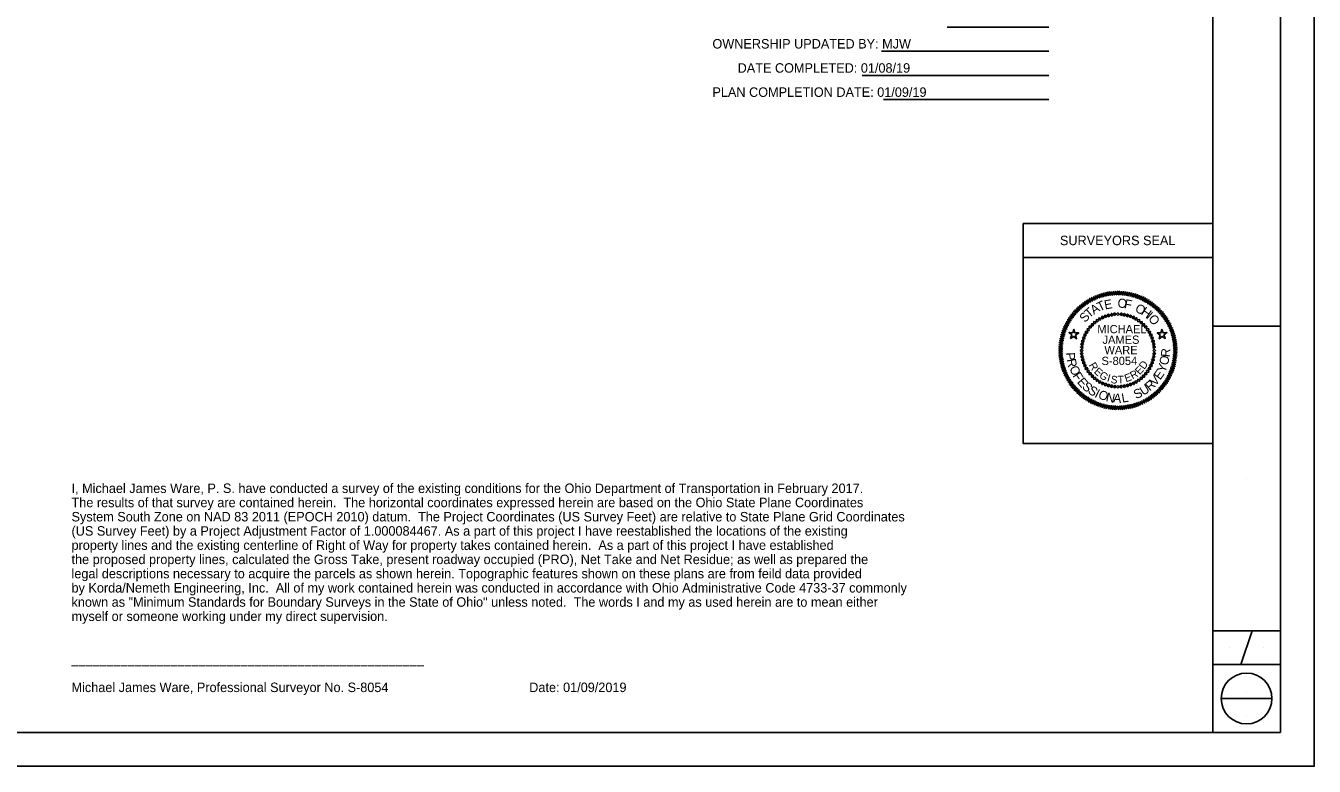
# Model space of a CAD drawing. Extents: x -0.4 to 33.6, y -0.9 to 21.1.
# Drawn here: x 14.55 to 33.59, y -0.92 to 10.01 of the extents above; entities that cross this region are included whole.
import ezdxf

# ---------------------------------------------------------------- set-up
doc = ezdxf.new("R2010")
doc.units = 0
for name, color, linetype in [('SH_Border', 7, 'Continuous'), ('SH_Cut_Line', 7, 'Continuous'), ('SH_Data', 7, 'Continuous'), ('SH_Text', 7, 'Continuous')]:
    doc.layers.add(name, color=color, linetype=linetype)

msp = doc.modelspace()

# ---------------------------------------------------------------- linework, layer by layer
at = {"layer": 'SH_Border'}
for p, q in [((32.087, -0.423), (32.087, 20.577)), ((32.087, 5.577), (33.087, 5.577)), ((32.087, 1.077), (33.087, 1.077)), ((32.504, 0.577), (32.67, 1.077)), ((32.087, 0.577), (33.087, 0.577))]:
    msp.add_line(p, q, dxfattribs=at)
msp.add_lwpolyline([(1.587, 20.577), (33.087, 20.577), (33.087, -0.423), (1.587, -0.423)], close=True, dxfattribs=at)
at = {"layer": 'SH_Cut_Line'}
msp.add_lwpolyline([(-0.413, -0.923), (33.587, -0.923), (33.587, 21.077), (-0.413, 21.077)], close=True, dxfattribs=at)
at = {"layer": 'SH_Data'}
for p, q in [((29.287, 6.592), (32.087, 6.592)), ((32.587, 3.327), (32.587, 3.327)), ((32.336, 0.827), (32.336, 0.827)), ((32.836, 0.827), (32.836, 0.827)), ((32.212, 0.077), (32.962, 0.077)), ((32.587, 0.162), (32.587, 0.162)), ((32.587, -0.178), (32.587, -0.178))]:
    msp.add_line(p, q, dxfattribs=at)
msp.add_lwpolyline([(29.287, 7.092), (32.087, 7.092), (32.087, 3.842), (29.287, 3.842)], close=True, dxfattribs=at)
msp.add_circle((32.587, 0.077), 0.375, dxfattribs=at)
at = {"layer": 'SH_Text'}
for p, q in [((28.162, 9.993), (29.665, 9.993)), ((27.192, 9.636), (29.665, 9.636)), ((26.906, 9.279), (29.665, 9.279)), ((27.221, 8.922), (29.665, 8.922)), ((30.641, 6.032), (30.614, 6.093)), ((30.67, 6.033), (30.645, 6.095)), ((30.698, 6.033), (30.675, 6.096)), ((30.727, 6.032), (30.706, 6.096)), ((30.755, 6.03), (30.737, 6.095)), ((30.784, 6.027), (30.767, 6.092)), ((30.194, 5.867), (30.137, 5.903)), ((30.217, 5.884), (30.161, 5.921)), ((30.24, 5.9), (30.186, 5.939)), ((30.264, 5.915), (30.211, 5.956)), ((30.289, 5.93), (30.238, 5.972)), ((30.314, 5.943), (30.264, 5.988)), ((30.339, 5.956), (30.291, 6.002)), ((30.365, 5.967), (30.319, 6.015)), ((30.392, 5.978), (30.347, 6.028)), ((30.419, 5.988), (30.376, 6.039)), ((30.446, 5.997), (30.404, 6.049)), ((30.473, 6.005), (30.434, 6.059)), ((30.501, 6.012), (30.463, 6.067)), ((30.528, 6.018), (30.493, 6.074)), ((30.556, 6.023), (30.523, 6.081)), ((30.585, 6.027), (30.553, 6.086)), ((30.613, 6.03), (30.584, 6.09)), ((30.812, 6.024), (30.798, 6.089)), ((30.84, 6.019), (30.828, 6.085)), ((30.868, 6.013), (30.858, 6.079)), ((30.895, 6.006), (30.888, 6.073)), ((30.923, 5.998), (30.918, 6.065)), ((30.95, 5.99), (30.948, 6.056)), ((30.977, 5.98), (30.977, 6.047)), ((31.003, 5.969), (31.005, 6.036)), ((31.029, 5.958), (31.034, 6.025)), ((31.055, 5.946), (31.062, 6.012)), ((31.08, 5.932), (31.089, 5.998)), ((31.105, 5.918), (31.116, 5.984)), ((31.129, 5.903), (31.143, 5.968)), ((31.153, 5.887), (31.169, 5.952)), ((31.176, 5.871), (31.194, 5.935)), ((31.198, 5.853), (31.219, 5.917)), ((30.033, 5.706), (29.969, 5.724)), ((30.051, 5.729), (29.987, 5.749)), ((30.069, 5.75), (30.006, 5.773)), ((30.088, 5.772), (30.026, 5.797)), ((30.108, 5.792), (30.047, 5.819)), ((30.128, 5.812), (30.068, 5.841)), ((30.149, 5.831), (30.09, 5.863)), ((30.171, 5.85), (30.113, 5.883)), ((31.22, 5.835), (31.243, 5.898)), ((31.241, 5.816), (31.266, 5.878)), ((31.262, 5.796), (31.289, 5.857)), ((31.282, 5.776), (31.311, 5.836)), ((31.301, 5.755), (31.332, 5.814)), ((31.319, 5.733), (31.353, 5.791)), ((31.337, 5.711), (31.372, 5.767)), ((31.354, 5.688), (31.391, 5.743)), ((31.37, 5.664), (31.409, 5.718)), ((29.935, 5.533), (29.868, 5.536)), ((29.946, 5.56), (29.879, 5.564)), ((29.959, 5.585), (29.892, 5.592)), ((29.972, 5.61), (29.906, 5.62)), ((29.986, 5.635), (29.92, 5.647)), ((30.001, 5.659), (29.936, 5.673)), ((30.017, 5.683), (29.952, 5.699)), ((31.385, 5.64), (31.426, 5.693)), ((31.399, 5.615), (31.442, 5.666)), ((31.413, 5.59), (31.457, 5.64)), ((31.425, 5.565), (31.472, 5.613)), ((31.437, 5.539), (31.485, 5.585)), ((31.448, 5.512), (31.497, 5.557)), ((31.457, 5.486), (31.509, 5.528)), ((29.88, 5.342), (29.815, 5.328)), ((29.885, 5.37), (29.819, 5.359)), ((29.891, 5.398), (29.825, 5.389)), ((29.898, 5.426), (29.831, 5.419)), ((29.906, 5.453), (29.839, 5.448)), ((29.914, 5.48), (29.848, 5.478)), ((29.924, 5.507), (29.857, 5.507)), ((31.466, 5.458), (31.519, 5.5)), ((31.474, 5.431), (31.528, 5.47)), ((31.481, 5.403), (31.537, 5.441)), ((31.487, 5.376), (31.544, 5.411)), ((31.492, 5.348), (31.55, 5.381)), ((31.496, 5.319), (31.555, 5.351)), ((29.872, 5.257), (29.808, 5.236)), ((29.871, 5.229), (29.808, 5.206)), ((29.874, 5.286), (29.809, 5.267)), ((29.871, 5.2), (29.809, 5.175)), ((29.872, 5.172), (29.811, 5.144)), ((29.877, 5.314), (29.812, 5.298)), ((29.874, 5.143), (29.814, 5.114)), ((31.499, 5.291), (31.56, 5.32)), ((31.5, 5.149), (31.564, 5.167)), ((31.502, 5.263), (31.563, 5.29)), ((31.502, 5.177), (31.565, 5.198)), ((31.503, 5.234), (31.565, 5.259)), ((31.503, 5.206), (31.566, 5.229)), ((29.877, 5.115), (29.818, 5.084)), ((29.881, 5.087), (29.823, 5.053)), ((29.886, 5.059), (29.83, 5.023)), ((29.892, 5.031), (29.837, 4.994)), ((29.899, 5.003), (29.845, 4.964)), ((29.907, 4.976), (29.855, 4.935)), ((31.459, 4.954), (31.526, 4.957)), ((31.468, 4.981), (31.535, 4.986)), ((31.476, 5.009), (31.542, 5.016)), ((31.483, 5.036), (31.549, 5.046)), ((31.488, 5.064), (31.554, 5.076)), ((31.493, 5.092), (31.559, 5.106)), ((31.497, 5.121), (31.562, 5.137)), ((29.916, 4.949), (29.865, 4.906)), ((29.926, 4.922), (29.876, 4.877)), ((29.937, 4.896), (29.889, 4.849)), ((29.948, 4.87), (29.902, 4.822)), ((29.961, 4.844), (29.916, 4.795)), ((29.975, 4.819), (29.932, 4.768)), ((29.989, 4.795), (29.948, 4.742)), ((30.004, 4.77), (29.965, 4.716)), ((31.373, 4.775), (31.438, 4.761)), ((31.388, 4.799), (31.454, 4.788)), ((31.402, 4.824), (31.468, 4.815)), ((31.415, 4.849), (31.482, 4.842)), ((31.428, 4.875), (31.494, 4.87)), ((31.439, 4.901), (31.506, 4.899)), ((31.45, 4.927), (31.517, 4.927)), ((30.02, 4.747), (29.983, 4.691)), ((30.037, 4.724), (30.001, 4.667)), ((30.054, 4.701), (30.021, 4.644)), ((30.073, 4.68), (30.041, 4.621)), ((30.092, 4.659), (30.063, 4.599)), ((30.112, 4.638), (30.085, 4.577)), ((30.132, 4.618), (30.107, 4.556)), ((30.154, 4.6), (30.131, 4.537)), ((30.176, 4.581), (30.155, 4.518)), ((31.203, 4.585), (31.26, 4.551)), ((31.224, 4.603), (31.283, 4.572)), ((31.245, 4.622), (31.306, 4.593)), ((31.266, 4.642), (31.327, 4.615)), ((31.286, 4.663), (31.348, 4.638)), ((31.305, 4.684), (31.367, 4.661)), ((31.323, 4.706), (31.386, 4.685)), ((31.34, 4.728), (31.404, 4.71)), ((31.357, 4.751), (31.422, 4.735)), ((30.198, 4.564), (30.18, 4.5)), ((30.221, 4.547), (30.205, 4.482)), ((30.245, 4.531), (30.231, 4.466)), ((30.269, 4.516), (30.257, 4.45)), ((30.294, 4.502), (30.284, 4.436)), ((30.319, 4.489), (30.312, 4.422)), ((30.345, 4.476), (30.34, 4.41)), ((30.371, 4.465), (30.368, 4.398)), ((30.397, 4.454), (30.397, 4.388)), ((30.424, 4.445), (30.426, 4.378)), ((30.451, 4.436), (30.456, 4.369)), ((30.478, 4.428), (30.485, 4.362)), ((30.506, 4.421), (30.515, 4.355)), ((30.534, 4.416), (30.546, 4.35)), ((30.562, 4.411), (30.576, 4.345)), ((30.59, 4.407), (30.606, 4.342)), ((30.619, 4.404), (30.637, 4.34)), ((30.647, 4.402), (30.668, 4.339)), ((30.675, 4.401), (30.698, 4.338)), ((30.704, 4.401), (30.729, 4.339)), ((30.732, 4.402), (30.76, 4.341)), ((30.761, 4.405), (30.79, 4.344)), ((30.789, 4.408), (30.82, 4.349)), ((30.817, 4.412), (30.851, 4.354)), ((30.845, 4.417), (30.881, 4.36)), ((30.873, 4.423), (30.911, 4.367)), ((30.901, 4.43), (30.94, 4.376)), ((30.928, 4.438), (30.969, 4.385)), ((30.955, 4.447), (30.998, 4.395)), ((30.982, 4.456), (31.027, 4.407)), ((31.008, 4.467), (31.055, 4.419)), ((31.034, 4.479), (31.082, 4.432)), ((31.06, 4.491), (31.109, 4.447)), ((31.085, 4.505), (31.136, 4.462)), ((31.11, 4.519), (31.162, 4.478)), ((31.134, 4.534), (31.188, 4.495)), ((31.157, 4.55), (31.213, 4.513)), ((31.18, 4.567), (31.237, 4.532))]:
    msp.add_line(p, q, dxfattribs=at)
for points in [[(30.469, 5.685), (30.478, 5.712), (30.452, 5.721), (30.442, 5.695)], [(30.51, 5.702), (30.522, 5.728), (30.497, 5.74), (30.485, 5.714)], [(30.553, 5.716), (30.567, 5.74), (30.543, 5.754), (30.529, 5.73)], [(30.597, 5.725), (30.613, 5.749), (30.59, 5.765), (30.574, 5.742)], [(30.642, 5.731), (30.66, 5.753), (30.638, 5.771), (30.62, 5.75)], [(30.687, 5.733), (30.707, 5.753), (30.687, 5.773), (30.667, 5.753)], [(30.732, 5.731), (30.753, 5.75), (30.735, 5.771), (30.714, 5.753)], [(30.776, 5.725), (30.8, 5.742), (30.783, 5.765), (30.76, 5.749)], [(30.82, 5.716), (30.845, 5.73), (30.831, 5.754), (30.806, 5.74)], [(30.863, 5.702), (30.889, 5.714), (30.877, 5.74), (30.851, 5.728)], [(30.905, 5.685), (30.932, 5.695), (30.922, 5.721), (30.895, 5.712)], [(30.052, 5.477), (30.107, 5.475), (30.062, 5.444), (30.077, 5.391), (30.034, 5.425), (29.988, 5.394), (30.007, 5.446), (29.964, 5.48), (30.019, 5.478), (30.037, 5.529)], [(30.264, 5.513), (30.259, 5.541), (30.231, 5.536), (30.236, 5.508)], [(30.291, 5.549), (30.289, 5.577), (30.261, 5.575), (30.263, 5.546)], [(30.322, 5.582), (30.322, 5.61), (30.294, 5.61), (30.294, 5.582)], [(30.355, 5.613), (30.358, 5.641), (30.329, 5.643), (30.327, 5.615)], [(30.391, 5.64), (30.396, 5.668), (30.368, 5.673), (30.363, 5.645)], [(30.429, 5.664), (30.436, 5.691), (30.409, 5.699), (30.401, 5.671)], [(30.945, 5.664), (30.972, 5.671), (30.965, 5.699), (30.938, 5.691)], [(30.983, 5.64), (31.011, 5.645), (31.006, 5.673), (30.978, 5.668)], [(31.019, 5.613), (31.047, 5.615), (31.044, 5.643), (31.016, 5.641)], [(31.052, 5.582), (31.08, 5.582), (31.08, 5.61), (31.052, 5.61)], [(31.082, 5.549), (31.11, 5.546), (31.113, 5.575), (31.085, 5.577)], [(31.11, 5.513), (31.137, 5.508), (31.142, 5.536), (31.115, 5.541)], [(31.34, 5.425), (31.297, 5.391), (31.312, 5.444), (31.267, 5.475), (31.321, 5.477), (31.336, 5.529), (31.355, 5.478), (31.41, 5.48), (31.367, 5.446), (31.385, 5.394)], [(30.188, 5.351), (30.174, 5.375), (30.15, 5.361), (30.164, 5.337)], [(30.202, 5.394), (30.19, 5.419), (30.164, 5.407), (30.176, 5.382)], [(30.219, 5.435), (30.209, 5.462), (30.183, 5.452), (30.193, 5.426)], [(30.24, 5.475), (30.233, 5.503), (30.205, 5.495), (30.213, 5.468)], [(31.134, 5.475), (31.161, 5.468), (31.168, 5.495), (31.141, 5.503)], [(31.155, 5.435), (31.181, 5.426), (31.191, 5.452), (31.164, 5.462)], [(31.172, 5.394), (31.197, 5.382), (31.209, 5.407), (31.184, 5.419)], [(31.185, 5.351), (31.21, 5.337), (31.224, 5.361), (31.2, 5.375)], [(30.171, 5.217), (30.151, 5.237), (30.131, 5.217), (30.151, 5.197)], [(30.173, 5.262), (30.155, 5.284), (30.133, 5.266), (30.151, 5.244)], [(30.173, 5.172), (30.151, 5.19), (30.133, 5.169), (30.155, 5.151)], [(30.179, 5.307), (30.162, 5.33), (30.139, 5.314), (30.155, 5.291)], [(30.179, 5.128), (30.155, 5.144), (30.139, 5.121), (30.162, 5.104)], [(31.195, 5.307), (31.218, 5.291), (31.234, 5.314), (31.211, 5.33)], [(31.195, 5.128), (31.211, 5.104), (31.234, 5.121), (31.218, 5.144)], [(31.201, 5.262), (31.223, 5.244), (31.241, 5.266), (31.219, 5.284)], [(31.201, 5.172), (31.219, 5.151), (31.241, 5.169), (31.223, 5.19)], [(31.203, 5.217), (31.223, 5.197), (31.243, 5.217), (31.223, 5.237)], [(30.188, 5.084), (30.164, 5.098), (30.15, 5.073), (30.174, 5.059)], [(30.202, 5.041), (30.176, 5.053), (30.164, 5.027), (30.19, 5.015)], [(30.219, 4.999), (30.193, 5.009), (30.183, 4.982), (30.209, 4.973)], [(30.24, 4.959), (30.213, 4.966), (30.205, 4.939), (30.233, 4.932)], [(31.134, 4.959), (31.141, 4.932), (31.168, 4.939), (31.161, 4.966)], [(31.155, 4.999), (31.164, 4.973), (31.191, 4.982), (31.181, 5.009)], [(31.172, 5.041), (31.184, 5.015), (31.209, 5.027), (31.197, 5.053)], [(31.185, 5.084), (31.2, 5.059), (31.224, 5.073), (31.21, 5.098)], [(30.264, 4.921), (30.236, 4.926), (30.231, 4.898), (30.259, 4.893)], [(30.291, 4.885), (30.263, 4.888), (30.261, 4.86), (30.289, 4.857)], [(30.322, 4.852), (30.294, 4.852), (30.294, 4.824), (30.322, 4.824)], [(30.355, 4.822), (30.327, 4.819), (30.329, 4.791), (30.358, 4.794)], [(30.391, 4.794), (30.363, 4.79), (30.368, 4.762), (30.396, 4.767)], [(30.429, 4.77), (30.401, 4.763), (30.409, 4.736), (30.436, 4.743)], [(30.945, 4.77), (30.938, 4.743), (30.965, 4.736), (30.972, 4.763)], [(30.983, 4.794), (30.978, 4.767), (31.006, 4.762), (31.011, 4.79)], [(31.019, 4.822), (31.016, 4.794), (31.044, 4.791), (31.047, 4.819)], [(31.052, 4.852), (31.052, 4.824), (31.08, 4.824), (31.08, 4.852)], [(31.082, 4.885), (31.085, 4.857), (31.113, 4.86), (31.11, 4.888)], [(31.11, 4.921), (31.115, 4.893), (31.142, 4.898), (31.137, 4.926)], [(30.469, 4.749), (30.442, 4.74), (30.452, 4.713), (30.478, 4.723)], [(30.51, 4.732), (30.485, 4.72), (30.497, 4.695), (30.522, 4.707)], [(30.553, 4.719), (30.529, 4.705), (30.543, 4.68), (30.567, 4.694)], [(30.597, 4.709), (30.574, 4.693), (30.59, 4.67), (30.613, 4.686)], [(30.642, 4.703), (30.62, 4.685), (30.638, 4.663), (30.66, 4.681)], [(30.687, 4.701), (30.667, 4.681), (30.687, 4.661), (30.707, 4.681)], [(30.732, 4.703), (30.714, 4.681), (30.735, 4.663), (30.753, 4.685)], [(30.776, 4.709), (30.76, 4.686), (30.783, 4.67), (30.8, 4.693)], [(30.82, 4.719), (30.806, 4.694), (30.831, 4.68), (30.845, 4.705)], [(30.863, 4.732), (30.851, 4.707), (30.877, 4.695), (30.889, 4.72)], [(30.905, 4.749), (30.895, 4.723), (30.922, 4.713), (30.932, 4.74)]]:
    msp.add_lwpolyline(points, close=True, dxfattribs=at)
for points in [[(30.007, 5.446), (29.988, 5.394), (30.034, 5.425), (30.077, 5.391), (30.062, 5.444), (30.107, 5.475), (30.052, 5.477), (30.037, 5.529), (30.019, 5.478), (29.964, 5.48), (30.007, 5.446)], [(31.355, 5.478), (31.336, 5.529), (31.321, 5.477), (31.267, 5.475), (31.312, 5.444), (31.297, 5.391), (31.34, 5.425), (31.385, 5.394), (31.367, 5.446), (31.41, 5.48), (31.355, 5.478)]]:
    msp.add_lwpolyline(points, dxfattribs=at)
for radius in [0.857, 0.837]:
    msp.add_circle((30.687, 5.217), radius, dxfattribs=at)

# ---------------------------------------------------------------- texts
at = {"layer": 'SH_Data'}
msp.add_text('SURVEYORS SEAL', height=0.14, dxfattribs=at).set_placement((29.83, 6.772))
at = {"layer": 'SH_Text'}
for s, height, p in [('OWNERSHIP UPDATED BY: MJW', 0.14, (24.696, 9.676)), ('DATE COMPLETED: 01/08/19', 0.14, (25.068, 9.319)), ('PLAN COMPLETION DATE: 01/09/19', 0.14, (24.696, 8.962)), ('MICHAEL', 0.1223, (30.382, 5.471)), ('JAMES', 0.1223, (30.459, 5.315)), ('WARE', 0.1223, (30.487, 5.162)), ('S-8054', 0.1223, (30.444, 5.002)), ('I, Michael James Ware, P. S. have conducted a survey of the existing conditions for the Ohio Department of Transportation in February 2017.', 0.14, (15.227, 3.112)), ('The results of that survey are contained herein.  The horizontal coordinates expressed herein are based on the Ohio State Plane Coordinates', 0.14, (15.227, 2.902)), ('System South Zone on NAD 83 2011 (EPOCH 2010) datum.  The Project Coordinates (US Survey Feet) are relative to State Plane Grid Coordinates', 0.14, (15.227, 2.692)), ('(US Survey Feet) by a Project Adjustment Factor of 1.000084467. As a part of this project I have reestablished the locations of the existing', 0.14, (15.227, 2.482)), ('property lines and the existing centerline of Right of Way for property takes contained herein.  As a part of this project I have established', 0.14, (15.227, 2.272)), ('the proposed property lines, calculated the Gross Take, present roadway occupied (PRO), Net Take and Net Residue; as well as prepared the', 0.14, (15.227, 2.062)), ('legal descriptions necessary to acquire the parcels as shown herein. Topographic features shown on these plans are from feild data provided', 0.14, (15.227, 1.852)), ('by Korda/Nemeth Engineering, Inc.  All of my work contained herein was conducted in accordance with Ohio Administrative Code 4733-37 commonly', 0.14, (15.227, 1.642)), ('known as "Minimum Standards for Boundary Surveys in the State of Ohio" unless noted.  The words I and my as used herein are to mean either', 0.14, (15.227, 1.432)), ('myself or someone working under my direct supervision.', 0.14, (15.227, 1.222)), ('__________________________________________________    ', 0.14, (15.227, 0.592)), ('Michael James Ware, Professional Surveyor No. S-8054                                        Date: 01/09/2019', 0.14, (15.227, 0.172))]:
    msp.add_text(s, height=height, dxfattribs=at).set_placement(p)
for s, height, rotation, p in [('T', 0.134, 25.6914, (30.416, 5.791)), ('E', 0.134, 10.7635, (30.497, 5.821)), ('O', 0.134, 355.8356, (30.677, 5.852)), ('F', 0.134, 348.3716, (30.772, 5.845)), ('O', 0.134, 333.4437, (30.929, 5.797)), ('S', 0.134, 48.0833, (30.202, 5.621)), ('T', 0.134, 40.6194, (30.263, 5.689)), ('A', 0.134, 33.1554, (30.331, 5.743)), ('H', 0.134, 325.9797, (31.017, 5.757)), ('I', 0.134, 318.5158, (31.092, 5.699)), ('O', 0.134, 311.0518, (31.126, 5.679)), ('P', 0.134, 272.8671, (29.916, 5.186)), ('R', 0.134, 84.5383, (31.452, 5.114)), ('R', 0.134, 280.3311, (29.93, 5.084)), ('O', 0.134, 295.259, (29.964, 4.955)), ('R', 0.112, 299.3103, (30.253, 5.002)), ('E', 0.112, 317.124, (30.324, 4.894)), ('E', 0.112, 46.1922, (31.007, 4.849)), ('D', 0.112, 55.099, (31.078, 4.928)), ('Y', 0.134, 69.6103, (31.383, 4.88)), ('O', 0.134, 77.0743, (31.423, 4.99)), ('F', 0.134, 302.723, (30.011, 4.843)), ('E', 0.134, 310.1869, (30.076, 4.747)), ('G', 0.112, 326.0308, (30.399, 4.826)), ('I', 0.112, 343.8444, (30.518, 4.764)), ('S', 0.112, 352.7513, (30.575, 4.737)), ('T', 0.112, 1.6581, (30.684, 4.73)), ('E', 0.112, 19.4717, (30.806, 4.747)), ('R', 0.112, 28.3786, (30.902, 4.788)), ('R', 0.134, 39.7545, (31.157, 4.611)), ('V', 0.134, 47.2185, (31.237, 4.684)), ('E', 0.134, 54.6824, (31.311, 4.773)), ('S', 0.134, 317.6509, (30.147, 4.669)), ('S', 0.134, 325.1149, (30.232, 4.598)), ('I', 0.134, 332.5788, (30.331, 4.533)), ('O', 0.134, 340.0428, (30.385, 4.513)), ('N', 0.134, 347.5067, (30.501, 4.469)), ('A', 0.134, 354.9707, (30.613, 4.452)), ('L', 0.134, 9.8986, (30.752, 4.445)), ('S', 0.134, 24.8266, (30.955, 4.496)), ('U', 0.134, 32.2905, (31.06, 4.546))]:
    msp.add_text(s, height=height, rotation=rotation, dxfattribs=at).set_placement(p)

doc.saveas('drawing.dxf')
